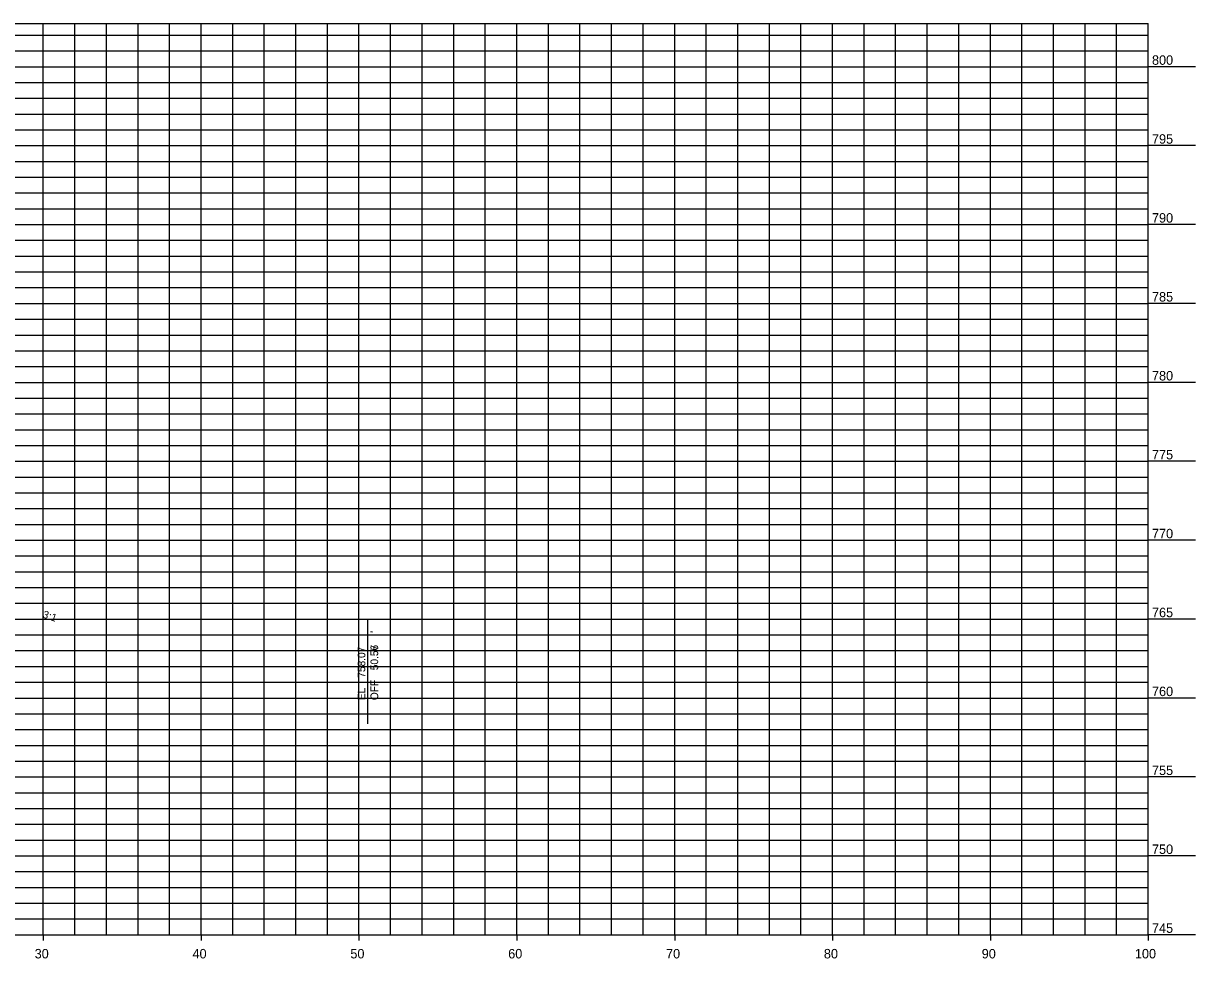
# Model space of a CAD drawing. Extents: x -43 to 103, y 742 to 803.
# Drawn here: x 28.7 to 103, y 743.5 to 802.7 of the extents above; entities that cross this region are included whole.
import ezdxf

# ---------------------------------------------------------------- set-up
doc = ezdxf.new("R2010")
doc.units = 0
for name, color, linetype in [('Default', 7, 'Continuous'), ('XS-Feature Text', 7, 'Continuous'), ('XS-Grid Lines', 7, 'Continuous'), ('XS-Segment Text', 7, 'Continuous'), ('XS-Sheet Major Grid Lines', 7, 'Continuous'), ('XS-Sheet Minor Grid Lines', 7, 'Continuous'), ('XS-Text', 7, 'Continuous')]:
    doc.layers.add(name, color=color, linetype=linetype)

msp = doc.modelspace()

# ---------------------------------------------------------------- linework, layer by layer
at = {"layer": 'XS-Feature Text'}
for p, q in [((50.561, 758.367), (50.561, 764.967)), ((50.567, 758.366), (50.567, 764.966)), ((50.568, 758.366), (50.568, 764.966))]:
    msp.add_line(p, q, dxfattribs=at)
at = {"layer": 'XS-Grid Lines'}
for p, q in [((-40, 802.74), (100, 802.74)), ((100, 745), (100, 802.74)), ((103, 800), (100, 800)), ((103, 795), (100, 795)), ((103, 790), (100, 790)), ((103, 785), (100, 785)), ((103, 780), (100, 780)), ((103, 775), (100, 775)), ((103, 770), (100, 770)), ((103, 765), (100, 765)), ((103, 760), (100, 760)), ((103, 755), (100, 755)), ((103, 750), (100, 750)), ((-40, 745), (100, 745)), ((30, 745), (30, 744.64)), ((40, 745), (40, 744.64)), ((50, 745), (50, 744.64)), ((60, 745), (60, 744.64)), ((70, 745), (70, 744.64)), ((80, 745), (80, 744.64)), ((90, 745), (90, 744.64)), ((100, 745), (100, 744.64)), ((103, 745), (100, 745))]:
    msp.add_line(p, q, dxfattribs=at)
at = {"layer": 'XS-Sheet Major Grid Lines'}
for p, q in [((30, 745), (30, 802.74)), ((40, 745), (40, 802.74)), ((50, 745), (50, 802.74)), ((60, 745), (60, 802.74)), ((70, 745), (70, 802.74)), ((80, 745), (80, 802.74)), ((90, 745), (90, 802.74)), ((-40, 800), (100, 800)), ((-40, 795), (100, 795)), ((-40, 790), (100, 790)), ((-40, 785), (100, 785)), ((-40, 780), (100, 780)), ((-40, 775), (100, 775)), ((-40, 770), (100, 770)), ((-40, 765), (100, 765)), ((-40, 760), (100, 760)), ((-40, 755), (100, 755)), ((-40, 750), (100, 750))]:
    msp.add_line(p, q, dxfattribs=at)
at = {"layer": 'XS-Sheet Minor Grid Lines'}
for p, q in [((32, 745), (32, 802.74)), ((34, 745), (34, 802.74)), ((36, 745), (36, 802.74)), ((38, 745), (38, 802.74)), ((42, 745), (42, 802.74)), ((44, 745), (44, 802.74)), ((46, 745), (46, 802.74)), ((48, 745), (48, 802.74)), ((52, 745), (52, 802.74)), ((54, 745), (54, 802.74)), ((56, 745), (56, 802.74)), ((58, 745), (58, 802.74)), ((62, 745), (62, 802.74)), ((64, 745), (64, 802.74)), ((66, 745), (66, 802.74)), ((68, 745), (68, 802.74)), ((72, 745), (72, 802.74)), ((74, 745), (74, 802.74)), ((76, 745), (76, 802.74)), ((78, 745), (78, 802.74)), ((82, 745), (82, 802.74)), ((84, 745), (84, 802.74)), ((86, 745), (86, 802.74)), ((88, 745), (88, 802.74)), ((92, 745), (92, 802.74)), ((94, 745), (94, 802.74)), ((96, 745), (96, 802.74)), ((98, 745), (98, 802.74)), ((-40, 802), (100, 802)), ((-40, 801), (100, 801)), ((-40, 799), (100, 799)), ((-40, 798), (100, 798)), ((-40, 797), (100, 797)), ((-40, 796), (100, 796)), ((-40, 794), (100, 794)), ((-40, 793), (100, 793)), ((-40, 792), (100, 792)), ((-40, 791), (100, 791)), ((-40, 789), (100, 789)), ((-40, 788), (100, 788)), ((-40, 787), (100, 787)), ((-40, 786), (100, 786)), ((-40, 784), (100, 784)), ((-40, 783), (100, 783)), ((-40, 782), (100, 782)), ((-40, 781), (100, 781)), ((-40, 779), (100, 779)), ((-40, 778), (100, 778)), ((-40, 777), (100, 777)), ((-40, 776), (100, 776)), ((-40, 774), (100, 774)), ((-40, 773), (100, 773)), ((-40, 772), (100, 772)), ((-40, 771), (100, 771)), ((-40, 769), (100, 769)), ((-40, 768), (100, 768)), ((-40, 767), (100, 767)), ((-40, 766), (100, 766)), ((-40, 764), (100, 764)), ((-40, 763), (100, 763)), ((-40, 762), (100, 762)), ((-40, 761), (100, 761)), ((-40, 759), (100, 759)), ((-40, 758), (100, 758)), ((-40, 757), (100, 757)), ((-40, 756), (100, 756)), ((-40, 754), (100, 754)), ((-40, 753), (100, 753)), ((-40, 752), (100, 752)), ((-40, 751), (100, 751)), ((-40, 749), (100, 749)), ((-40, 748), (100, 748)), ((-40, 747), (100, 747)), ((-40, 746), (100, 746))]:
    msp.add_line(p, q, dxfattribs=at)

# ---------------------------------------------------------------- texts
at = {"layer": 'Default'}
for s, p in [('800', (100.24, 800.12)), ('795', (100.24, 795.12)), ('790', (100.24, 790.12)), ('785', (100.24, 785.12)), ('780', (100.24, 780.12)), ('775', (100.24, 775.12)), ('770', (100.24, 770.12)), ('765', (100.24, 765.12)), ('760', (100.24, 760.12)), ('755', (100.24, 755.12)), ('750', (100.24, 750.12)), ('745', (100.24, 745.12))]:
    msp.add_text(s, height=0.6, dxfattribs=at).set_placement(p)
at = {"layer": 'XS-Feature Text'}
for s, p in [("'", (51.209, 764.129)), ("'", (51.215, 764.128)), ("'", (51.216, 764.128)), ('758.07', (50.393, 761.287)), ('758.07', (50.399, 761.287)), ('758.07', (50.4, 761.287)), ('50.56', (51.209, 761.761)), ('50.57', (51.215, 761.76)), ('50.57', (51.216, 761.76)), ('EL ', (50.393, 759.867)), ('EL ', (50.399, 759.866)), ('EL ', (50.4, 759.866)), ('OFF ', (51.209, 759.867)), ('OFF ', (51.215, 759.866)), ('OFF ', (51.216, 759.866))]:
    msp.add_text(s, height=0.48, rotation=90, dxfattribs=at).set_placement(p)
at = {"layer": 'XS-Segment Text'}
msp.add_text('3:1', height=0.48, rotation=341.56677, dxfattribs=at).set_placement((29.92, 765.104))
at = {"layer": 'XS-Text'}
for s, p in [('30', (29.453, 743.5)), ('40', (39.453, 743.5)), ('50', (49.453, 743.5)), ('60', (59.453, 743.5)), ('70', (69.453, 743.5)), ('80', (79.453, 743.5)), ('90', (89.453, 743.5)), ('100', (99.157, 743.5))]:
    msp.add_text(s, height=0.6, dxfattribs=at).set_placement(p)

doc.saveas('drawing.dxf')
